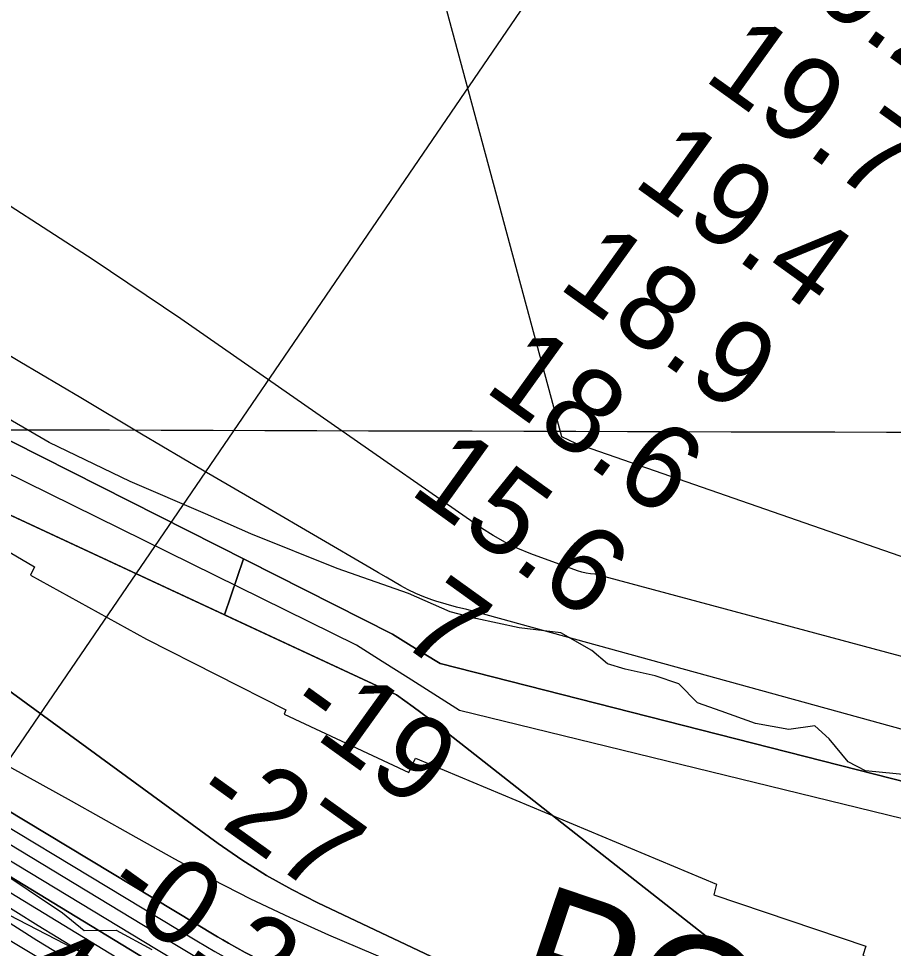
# Model space of a CAD drawing. Extents: x 3161615 to 3199515, y 867541 to 892976.
# Drawn here: x 3183041 to 3183730, y 878610 to 879343 of the extents above; entities that cross this region are included whole.
import ezdxf

# ---------------------------------------------------------------- set-up
doc = ezdxf.new("R2010")
doc.units = 0
for name, color, linetype in [('V-GRID-MAJR', 7, 'Continuous'), ('V-RIVR-EDGE', 7, 'Continuous'), ('V-RIVR-RANG', 7, 'Continuous'), ('V-RRAP-RVMT', 7, 'Continuous'), ('V-RRAP-RVMT-IDEN', 7, 'Continuous'), ('V-TOPO-DPTH', 7, 'Continuous'), ('V-TOPO-MAJR', 7, 'Continuous'), ('V-TOPO-MINR', 7, 'Continuous'), ('V-TOPO-WATR', 7, 'Continuous')]:
    doc.layers.add(name, color=color, linetype=linetype)

msp = doc.modelspace()

# ---------------------------------------------------------------- linework, layer by layer
at = {"layer": 'V-GRID-MAJR'}
msp.add_spline([(3165838.644, 879070.158), (3171065.6580000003, 879053.813), (3176292.6750000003, 879038.2270000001), (3181519.694, 879023.402), (3186746.716, 879009.337), (3191973.739, 878996.033), (3197200.764, 878983.488), (3197200.765, 878983.488)], degree=3, dxfattribs=at)
at = {"layer": 'V-RIVR-EDGE'}
for points in [[(3183468.187514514, 878859.16200803), (3183435.292743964, 878863.0583508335), (3183400.9756100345, 878870.2963387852), (3183380.959935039, 878875.5914615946), (3183348.0911062, 878889.978999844), (3183291.868494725, 878909.6699150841), (3183223.7429369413, 878937.0202698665), (3183188.0164104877, 878952.8455006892), (3183128.469841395, 878978.2671403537), (3183064.644390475, 879008.9449902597), (3183017.978096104, 879036.2422824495)], [(3183743.0670332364, 878746.8934579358), (3183708.263593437, 878750.3176448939), (3183694.45197788, 878757.5049285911), (3183679.713738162, 878775.6626385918), (3183668.293560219, 878785.7052615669), (3183647.780966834, 878782.8947307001), (3183621.564769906, 878787.7283101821), (3183594.4066196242, 878797.332973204), (3183575.8250996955, 878804.0551760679), (3183561.0786057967, 878818.8747784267), (3183542.495906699, 878825.1201087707), (3183518.665251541, 878830.4246649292), (3183504.846560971, 878834.7507135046), (3183492.473817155, 878845.2725673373), (3183468.187514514, 878859.16200803)], [(3182939.012797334, 878729.8066355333), (3182980.9068289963, 878701.0905174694), (3183019.9467005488, 878675.24270954), (3183075.1731169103, 878638.3867419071), (3183092.306331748, 878624.514988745), (3183117.581754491, 878624.929365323), (3183145.679499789, 878609.59987372)]]:
    msp.add_lwpolyline(points, dxfattribs=at)
at = {"layer": 'V-RIVR-RANG'}
msp.add_line((3182760.724000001, 878360.6329999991), (3184853.5152000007, 881422.8063999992), dxfattribs=at)
at = {"layer": 'V-RRAP-RVMT'}
for points in [[(3182576.939000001, 879156.3019999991), (3182585.417000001, 879168.8699999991), (3182687.606000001, 879096.964999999), (3182703.933000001, 879120.052999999), (3182808.001000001, 879050.074999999), (3182809.801000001, 879052.3659999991), (3182914.981000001, 878984.684999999), (3182918.247000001, 878990.302999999), (3183053.184000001, 878911.0739999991), (3183050.133000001, 878904.623999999), (3183141.405000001, 878854.1079999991), (3183251.383000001, 878798.2869999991), (3183250.100000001, 878794.998999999), (3183348.272000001, 878749.153999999), (3183353.429000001, 878760.4029999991), (3183590.870000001, 878661.023999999), (3183588.5900000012, 878652.5619999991), (3183708.576000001, 878612.0739999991), (3183706.105000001, 878604.868999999), (3183832.337000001, 878563.8749999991)], [(3183743.901000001, 878338.0819999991), (3183618.972000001, 878377.787999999), (3183621.186000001, 878385.662999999), (3183495.822000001, 878428.6739999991), (3183498.039000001, 878436.893999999), (3183377.367000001, 878484.3749999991), (3183266.119000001, 878531.6419999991), (3183261.453000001, 878520.9559999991), (3183134.545000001, 878579.2899999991), (3183136.280000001, 878583.322999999), (3183018.175000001, 878644.3659999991), (3183019.270000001, 878646.9269999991), (3182903.217000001, 878711.229999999), (3182905.703000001, 878715.498999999), (3182807.775000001, 878772.9239999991), (3182804.015000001, 878766.3999999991), (3182686.033000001, 878843.5399999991), (3182681.696000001, 878838.1149999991), (3182573.619000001, 878909.9139999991), (3182561.916000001, 878892.694999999), (3182455.520000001, 878966.988999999), (3182444.712000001, 878952.829999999)]]:
    msp.add_lwpolyline(points, dxfattribs=at)
at = {"layer": 'V-TOPO-DPTH'}
for points in [[(3184008.2494205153, 878283.5851602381), (3183219.0654344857, 878556.6295615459), (3183197.5407897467, 878568.8376126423), (3183176.1025140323, 878581.1937332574), (3183154.7937918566, 878593.7719581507), (3183133.5714387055, 878606.4982525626), (3182990.8766900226, 878693.0784576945), (3182898.882719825, 878749.995557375), (3182807.5695592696, 878807.9647516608), (3182717.2776131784, 878867.5120878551), (3182627.6664767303, 878928.1115186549), (3182398.3942631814, 879086.0775906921), (3182385.8349131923, 879095.1037964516), (3182373.5292961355, 879104.4506397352), (3182361.604278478, 879114.2784393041), (3182349.9329937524, 879124.4268763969), (3181936.2970125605, 879498.7721583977)], [(3183217.9652991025, 878917.3250613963), (3182552.2200174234, 879253.8147654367), (3182538.7632044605, 879259.7528369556), (3182522.623452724, 879267.8725038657), (3182517.539286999, 879270.6020290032), (3182512.5625776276, 879273.5050143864), (3182507.747052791, 879276.6681901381), (3182503.0389843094, 879280.0048261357), (3182204.5411575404, 879503.7086609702)], [(3182204.5411575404, 879503.7086609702), (3182503.0389843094, 879280.0048261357), (3182507.747052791, 879276.6681901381), (3182512.5625776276, 879273.5050143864), (3182517.539286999, 879270.6020290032), (3182522.623452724, 879267.8725038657), (3182538.7632044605, 879259.7528369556), (3182552.2200174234, 879253.8147654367), (3183335.393884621, 878857.9727669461), (3183347.873590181, 878850.2512727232), (3183360.358108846, 878842.5375766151), (3183372.849847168, 878834.8355776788), (3184249.570273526, 878611.664489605)], [(3182122.640815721, 879346.9773454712), (3182207.6923048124, 879267.9705426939), (3182364.5242987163, 879125.5243326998), (3182372.197901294, 879118.831860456), (3182380.0412273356, 879112.3535152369), (3182388.1391385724, 879106.1963605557), (3182396.4067732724, 879100.2533328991), (3182521.671060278, 879013.9851356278), (3182593.1151253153, 878965.7141486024), (3182665.1141369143, 878918.3024508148), (3182737.9455683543, 878872.1796868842), (3182811.331946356, 878826.9162121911), (3183165.215166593, 878612.9713359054), (3183176.9925421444, 878605.9342887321), (3183188.8175730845, 878598.9792354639), (3183200.714087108, 878592.147173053), (3183212.658256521, 878585.3971045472), (3184036.985233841, 878291.612818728)], [(3182122.640815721, 879346.9773454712), (3182207.6923048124, 879267.9705426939), (3182364.5242987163, 879125.5243326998), (3182372.197901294, 879118.831860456), (3182380.0412273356, 879112.3535152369), (3182388.1391385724, 879106.1963605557), (3182396.4067732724, 879100.2533328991), (3182521.671060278, 879013.9851356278), (3182593.1151253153, 878965.7141486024), (3182665.1141369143, 878918.3024508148), (3182737.9455683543, 878872.1796868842), (3182811.331946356, 878826.9162121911), (3183165.215166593, 878612.9713359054), (3183176.9925421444, 878605.9342887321), (3183188.8175730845, 878598.9792354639), (3183200.714087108, 878592.147173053), (3183212.658256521, 878585.3971045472), (3184036.985233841, 878291.612818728)], [(3184294.458670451, 878690.6435393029), (3183495.1305291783, 878905.2467260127), (3183491.59184058, 878905.5155059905), (3183488.0964737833, 878906.0101828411), (3183484.666089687, 878906.8437050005), (3183481.2790273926, 878907.9031240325), (3183444.4242281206, 878921.4481801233), (3183434.251981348, 878925.6372584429), (3183424.3386775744, 878930.3237506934), (3183414.813788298, 878935.7563638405), (3183405.5478420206, 878941.6863909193), (3183168.413472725, 879106.6304329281), (3183099.3726196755, 879153.1138748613), (3183029.4415142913, 879198.1683294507), (3182958.1750304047, 879241.0793030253), (3182886.018294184, 879282.5612892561), (3182794.313225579, 879333.4445188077), (3182767.148227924, 879348.0239253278)], [(3184294.458670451, 878690.6435393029), (3183495.1305291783, 878905.2467260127), (3183491.59184058, 878905.5155059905), (3183488.0964737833, 878906.0101828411), (3183484.666089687, 878906.8437050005), (3183481.2790273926, 878907.9031240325), (3183444.4242281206, 878921.4481801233), (3183434.251981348, 878925.6372584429), (3183424.3386775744, 878930.3237506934), (3183414.813788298, 878935.7563638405), (3183405.5478420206, 878941.6863909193), (3183168.413472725, 879106.6304329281), (3183099.3726196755, 879153.1138748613), (3183029.4415142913, 879198.1683294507), (3182958.1750304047, 879241.0793030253), (3182886.018294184, 879282.5612892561), (3182794.313225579, 879333.4445188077), (3182767.148227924, 879348.0239253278)], [(3183395.8027375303, 878589.9030205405), (3183276.398417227, 878646.3923043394), (3183255.9948417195, 878656.7628188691), (3183236.031921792, 878667.874772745), (3183216.729985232, 878680.0988856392), (3183197.868704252, 878693.0644378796), (3182760.1208189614, 879012.6225637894), (3182752.8281949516, 879022.6947560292), (3182749.5844254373, 879032.8490396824), (3182752.4139376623, 879043.126460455), (3182759.2923043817, 879053.4859726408), (3182773.0166985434, 879061.4175533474), (3182787.3135431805, 879066.518734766), (3183203.0249776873, 878873.1912710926), (3183217.9652991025, 878917.3250613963)], [(3183608.358843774, 878599.779189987), (3183364.770060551, 878791.0830718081), (3183351.7370305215, 878800.7641076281), (3183338.5202823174, 878810.1788990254), (3182787.3135431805, 879066.518734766), (3182773.0166985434, 879061.4175533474), (3182759.2923043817, 879053.4859726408), (3182752.4139376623, 879043.126460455), (3182749.5844254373, 879032.8490396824), (3182752.8281949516, 879022.6947560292), (3182760.1208189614, 879012.6225637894), (3183197.868704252, 878693.0644378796), (3183216.729985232, 878680.0988856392), (3183236.031921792, 878667.874772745), (3183255.9948417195, 878656.7628188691), (3183276.398417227, 878646.3923043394), (3183395.8027375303, 878589.9030205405)], [(3182593.3859588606, 878983.5473735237), (3183197.4894567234, 878619.6279987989), (3183201.7717963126, 878617.0983577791), (3183206.0971439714, 878614.6429792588), (3183219.349253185, 878607.2705676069), (3183223.3444582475, 878605.1383263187), (3183227.3853731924, 878603.1008115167), (3183231.4948529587, 878601.205386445), (3183235.6500426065, 878599.4046878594), (3183239.8590646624, 878597.7285646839), (3183244.0939870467, 878596.123445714), (3183248.3677599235, 878594.6248330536), (3183252.667433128, 878593.1972245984), (3184062.4632930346, 878298.5288033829)], [(3184062.4632930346, 878298.5288033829), (3183252.667433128, 878593.1972245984), (3183248.3677599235, 878594.6248330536), (3183244.0939870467, 878596.123445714), (3183239.8590646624, 878597.7285646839), (3183235.6500426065, 878599.4046878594), (3183231.4948529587, 878601.205386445), (3183227.3853731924, 878603.1008115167), (3183223.3444582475, 878605.1383263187), (3183219.349253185, 878607.2705676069), (3183206.0971439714, 878614.6429792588), (3183201.7717963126, 878617.0983577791), (3183197.4894567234, 878619.6279987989), (3182593.3859588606, 878983.5473735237)], [(3183221.151293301, 878915.7147544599), (3183217.9652991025, 878917.3250613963), (3183203.0249776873, 878873.1912710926), (3183207.9474508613, 878870.9020647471), (3183338.5202823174, 878810.1788990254), (3183351.7370305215, 878800.7641076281), (3183364.770060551, 878791.0830718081), (3183608.358843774, 878599.779189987), (3183608.4890395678, 878594.0807626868)], [(3183865.506115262, 878709.428854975), (3183372.849847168, 878834.8355776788), (3183360.358108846, 878842.5375766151), (3183347.873590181, 878850.2512727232), (3183335.393884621, 878857.9727669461), (3183221.151293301, 878915.7147544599)]]:
    msp.add_lwpolyline(points, dxfattribs=at)
at = {"layer": 'V-TOPO-MAJR'}
msp.add_lwpolyline([(3181603.130684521, 879751.2716691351), (3182052.7917978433, 879323.7952983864), (3182100.2796248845, 879280.0808535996), (3182148.6640860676, 879237.4167917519), (3182198.393498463, 879196.3283043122), (3182249.0195450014, 879156.2901998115), (3182300.4335544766, 879116.9546378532), (3182326.2265106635, 879097.6554457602), (3182352.2856267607, 879078.7311380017), (3182378.7439827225, 879060.3691567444), (3182405.4684985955, 879042.3820598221), (3182954.387044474, 878681.4094726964), (3182987.8046574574, 878659.6764932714), (3183021.3669463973, 878638.1718581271), (3183055.146249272, 878617.0097394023), (3183089.0702281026, 878596.0759649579), (3183123.2077182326, 878575.4924747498), (3183157.4851443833, 878555.1475713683), (3183191.9724745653, 878535.1605482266), (3183235.315423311, 878518.6069014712), (3184012.537934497, 878243.9726394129)], dxfattribs=at)
at = {"layer": 'V-TOPO-MINR'}
for points in [[(3184320.1501716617, 878716.46733833), (3183479.786941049, 879008.278451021), (3183468.9847077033, 879013.6002346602), (3183197.678490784, 880018.7165242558)], [(3181661.887512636, 879726.5492312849), (3182335.2285819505, 879123.2036345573), (3182350.945366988, 879109.6523397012), (3182366.9883619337, 879096.5152845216), (3182383.5206717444, 879083.9995888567), (3182400.3791914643, 879071.8981328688), (3182845.76225625, 878764.8971536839), (3182897.692606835, 878729.7476307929), (3182950.0086064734, 878695.192888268), (3183002.9030796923, 878661.5303162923), (3183056.183201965, 878628.4625246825), (3183102.576379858, 878600.2111991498), (3183186.1905660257, 878548.365111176), (3184038.509437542, 878244.2763951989)], [(3181770.3393400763, 879640.7924820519), (3182342.626229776, 879123.8658212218), (3182356.301000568, 879111.9945298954), (3182370.270306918, 879100.495765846), (3182384.6814166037, 879089.555792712), (3182399.3870618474, 879078.9883468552), (3182736.512070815, 878846.6615924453), (3182807.3149272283, 878798.759748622), (3182878.649643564, 878751.6790023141), (3182950.7821497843, 878705.8299022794), (3183023.446515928, 878660.8018997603), (3183117.9931251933, 878603.3316264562), (3183143.8625232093, 878587.7904831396), (3183169.8374538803, 878572.4299334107), (3183195.9706835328, 878557.3402740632), (3184018.6414099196, 878266.3728113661)], [(3181936.2970125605, 879498.7721583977), (3182349.9329937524, 879124.4268763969), (3182361.604278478, 879114.2784393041), (3182373.5292961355, 879104.4506397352), (3182385.8349131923, 879095.1037964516), (3182398.3942631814, 879086.0775906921), (3182627.6664767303, 878928.1115186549), (3182717.2776131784, 878867.5120878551), (3182807.5695592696, 878807.9647516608), (3182898.882719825, 878749.995557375), (3182990.8766900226, 878693.0784576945), (3183133.5714387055, 878606.4982525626), (3183154.7937918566, 878593.7719581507), (3183176.1025140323, 878581.1937332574), (3183197.5407897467, 878568.8376126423), (3183219.0654344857, 878556.6295615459), (3184008.2494205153, 878283.5851602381)], [(3184249.570273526, 878611.664489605), (3183372.849847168, 878834.8355776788), (3183360.358108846, 878842.5375766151), (3183347.873590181, 878850.2512727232), (3183335.393884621, 878857.9727669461), (3182552.2200174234, 879253.8147654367), (3182538.7632044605, 879259.7528369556), (3182522.623452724, 879267.8725038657), (3182517.539286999, 879270.6020290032), (3182512.5625776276, 879273.5050143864), (3182507.747052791, 879276.6681901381), (3182503.0389843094, 879280.0048261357), (3182204.5411575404, 879503.7086609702)], [(3184133.4865874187, 878615.7380625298), (3183388.1043961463, 878797.7976993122), (3183367.8688096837, 878810.7333122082), (3183347.6071419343, 878823.6278045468), (3183327.3063522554, 878836.4606160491), (3183306.97948129, 878849.2523069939), (3182599.954990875, 879197.7283670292), (3182531.4329247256, 879229.8109115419), (3182511.9326996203, 879239.5091757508), (3182492.770591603, 879249.8027186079), (3182474.115659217, 879260.9891794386), (3182455.7988439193, 879272.7709189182), (3182372.739833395, 879329.0137760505), (3182313.3724682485, 879369.6840788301)], [(3182094.021329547, 879363.6272264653), (3182357.232179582, 879124.9795170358), (3182366.9031468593, 879116.557435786), (3182376.7862254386, 879108.4031715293), (3182386.987470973, 879100.6506327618), (3182397.4008278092, 879093.1659109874), (3182555.46329748, 878984.2863396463), (3182645.5872241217, 878923.3672984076), (3182736.4035368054, 878863.5193013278), (3182828.258428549, 878805.2778704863), (3182920.805706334, 878748.1074838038), (3183149.3118834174, 878609.7114007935), (3183165.836977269, 878599.8198014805), (3183182.429157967, 878590.0434237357), (3183199.1219689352, 878580.4398783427), (3184022.996397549, 878287.731168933)], [(3182135.36622271, 879345.2175824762), (3182196.328837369, 879286.9261439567), (3182258.126821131, 879229.489964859), (3182371.809797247, 879126.0618367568), (3182377.4887985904, 879121.1020088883), (3182383.29441407, 879116.301800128), (3182389.2899507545, 879111.7410200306), (3182395.412101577, 879107.3398590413), (3182488.002465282, 879043.5875340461), (3182540.8264218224, 879007.9128781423), (3182594.0651348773, 878972.8810682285), (3182647.925982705, 878938.8135273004), (3182702.2015870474, 878905.3888323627), (3183181.2747555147, 878616.2769413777), (3183188.2559413, 878612.1130947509), (3183195.2652931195, 878607.9977958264), (3183202.316893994, 878603.9553184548), (3183209.3966609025, 878599.9613887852), (3184050.155685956, 878295.2155285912)], [(3184277.182839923, 878634.3805067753), (3183394.0893720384, 878877.4493847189), (3183385.861650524, 878879.3211374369), (3183377.7245836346, 878881.5542970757), (3183369.6479531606, 878884.0283946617), (3183366.4130131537, 878885.0980821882), (3183360.0896032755, 878887.4174254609), (3183353.885339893, 878889.9990079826), (3183347.8597962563, 878892.9739493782), (3183341.9533991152, 878896.2111300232), (3183336.1338839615, 878899.641189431), (3183330.309920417, 878903.0636621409), (3183324.4792842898, 878906.4747548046), (3183318.6441997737, 878909.8782607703), (3183233.8735861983, 878959.2126520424), (3183185.706990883, 878987.3743356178), (3183137.6165691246, 879015.664910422), (3183089.640407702, 879044.1488220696), (3183041.7404198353, 879072.7616249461), (3182657.5274817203, 879303.3195961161)], [(3183608.358843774, 878599.779189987), (3183364.770060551, 878791.0830718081), (3183351.7370305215, 878800.7641076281), (3183338.5202823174, 878810.1788990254), (3182787.3135431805, 879066.518734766), (3182773.0166985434, 879061.4175533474), (3182759.2923043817, 879053.4859726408), (3182752.4139376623, 879043.126460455), (3182749.5844254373, 879032.8490396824), (3182752.8281949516, 879022.6947560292), (3182760.1208189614, 879012.6225637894), (3183197.868704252, 878693.0644378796), (3183216.729985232, 878680.0988856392), (3183236.031921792, 878667.874772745), (3183255.9948417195, 878656.7628188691), (3183276.398417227, 878646.3923043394), (3183395.8027375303, 878589.9030205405)], [(3182593.3859588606, 878983.5473735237), (3183197.4894567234, 878619.6279987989), (3183201.7717963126, 878617.0983577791), (3183206.0971439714, 878614.6429792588), (3183219.349253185, 878607.2705676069), (3183223.3444582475, 878605.1383263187), (3183227.3853731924, 878603.1008115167), (3183231.4948529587, 878601.205386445), (3183235.6500426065, 878599.4046878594), (3183239.8590646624, 878597.7285646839), (3183244.0939870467, 878596.123445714), (3183248.3677599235, 878594.6248330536), (3183252.667433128, 878593.1972245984), (3184062.4632930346, 878298.5288033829)], [(3182646.444139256, 878967.3523891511), (3182711.5049258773, 878930.1723711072), (3182776.9457829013, 878893.6654686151), (3182842.6400201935, 878857.6073098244), (3182940.851711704, 878804.3583614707), (3182988.0234364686, 878778.6402172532), (3183035.114514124, 878752.7760452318), (3183082.084621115, 878726.6928315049), (3183128.974080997, 878700.463589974), (3183163.481042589, 878681.055287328), (3183193.3017712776, 878664.9182484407), (3183223.4486777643, 878649.4430107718), (3183254.084850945, 878634.9604749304), (3183285.0472019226, 878621.1397403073), (3183431.191191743, 878558.7478869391), (3184073.839320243, 878301.5371289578)], [(3182633.0394740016, 878849.9694619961), (3182710.440217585, 878806.392119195), (3182787.5713471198, 878762.3475808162), (3182864.2980555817, 878717.6022490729), (3182940.755149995, 878672.3897217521), (3183064.2163638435, 878598.6204784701), (3183078.7275299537, 878589.9204766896), (3183093.221267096, 878581.1916326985), (3183107.6888607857, 878572.4195253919), (3183122.1390255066, 878563.6185758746), (3183136.620656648, 878554.871795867), (3183151.161657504, 878546.2260594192), (3183165.791712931, 878537.7318883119), (3183180.481138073, 878529.3387607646), (3183995.4675630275, 878238.5669210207)]]:
    msp.add_lwpolyline(points, dxfattribs=at)
at = {"layer": 'V-TOPO-WATR'}
for points in [[(3182122.640815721, 879346.9773454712), (3182207.6923048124, 879267.9705426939), (3182364.5242987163, 879125.5243326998), (3182372.197901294, 879118.831860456), (3182380.0412273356, 879112.3535152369), (3182388.1391385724, 879106.1963605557), (3182396.4067732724, 879100.2533328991), (3182521.671060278, 879013.9851356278), (3182593.1151253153, 878965.7141486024), (3182665.1141369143, 878918.3024508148), (3182737.9455683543, 878872.1796868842), (3182811.331946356, 878826.9162121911), (3183165.215166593, 878612.9713359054), (3183176.9925421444, 878605.9342887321), (3183188.8175730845, 878598.9792354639), (3183200.714087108, 878592.147173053), (3183212.658256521, 878585.3971045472), (3184036.985233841, 878291.612818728)], [(3184294.458670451, 878690.6435393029), (3183495.1305291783, 878905.2467260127), (3183491.59184058, 878905.5155059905), (3183488.0964737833, 878906.0101828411), (3183484.666089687, 878906.8437050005), (3183481.2790273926, 878907.9031240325), (3183444.4242281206, 878921.4481801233), (3183434.251981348, 878925.6372584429), (3183424.3386775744, 878930.3237506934), (3183414.813788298, 878935.7563638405), (3183405.5478420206, 878941.6863909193), (3183168.413472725, 879106.6304329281), (3183099.3726196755, 879153.1138748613), (3183029.4415142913, 879198.1683294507), (3182958.1750304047, 879241.0793030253), (3182886.018294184, 879282.5612892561), (3182794.313225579, 879333.4445188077), (3182767.148227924, 879348.0239253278)]]:
    msp.add_lwpolyline(points, dxfattribs=at)

# ---------------------------------------------------------------- texts
at = {"layer": 'V-RIVR-RANG'}
for s, rotation, p in [('20.2', 324.30499999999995, (3183622.830640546, 879387.6017858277)), ('19.7', 324.30499999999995, (3183579.309902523, 879295.7370737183)), ('19.4', 324.30499999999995, (3183523.5793713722, 879212.6450908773)), ('18.9', 324.30499999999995, (3183464.6344736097, 879131.8617210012)), ('18.6', 324.30499999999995, (3183406.333249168, 879050.6156285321)), ('15.6', 324.30499999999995, (3183347.3883514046, 878969.8322586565)), ('7', 324.30499999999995, (3183338.5729727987, 878853.0345265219)), ('-19', 324.30499999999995, (3183248.9939799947, 878794.2599335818)), ('-27', 324.30499999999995, (3183174.8391469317, 878724.4029984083)), ('-0.2', 324.30499999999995, (3183104.755578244, 878651.6228201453)), ('45.7', 324.3483257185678, (3183030.568979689, 878581.6791963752))]:
    msp.add_text(s, height=67, rotation=rotation, dxfattribs=at).set_placement(p)
at = {"layer": 'V-RRAP-RVMT-IDEN'}
msp.add_text('POINT', height=99.99980200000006, rotation=341.3901455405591, dxfattribs=at).set_placement((3183424.522188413, 878567.5297919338))

doc.saveas('drawing.dxf')
